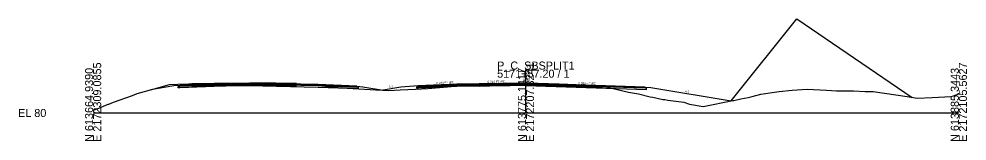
# Model space of a CAD drawing. Extents: x -26 to 1303, y -3010 to 12033.
# Drawn here: x -25.7 to 302.8, y -9.7 to 32.5 of the extents above; entities that cross this region are included whole.
import ezdxf

# ---------------------------------------------------------------- set-up
doc = ezdxf.new("R2010")
doc.units = 0
for name, color, linetype in [('RD_GPK_XS_Cell', 7, 'Continuous'), ('RD_Sketch10', 7, 'Continuous'), ('RD_XS_Base', 7, 'Continuous'), ('RD_XS_Buildup', 7, 'Continuous'), ('RD_XS_ExGround', 7, 'Continuous'), ('RD_XS_ExPaveRet', 7, 'Continuous'), ('RD_XS_Greenside', 7, 'Continuous'), ('RD_XS_Pave', 7, 'Continuous'), ('RD_XS_PaveOvlay_CP', 7, 'Continuous'), ('RD_XS_TieSlope', 7, 'Continuous'), ('RD_XS_TX_Elev_EX', 7, 'Continuous'), ('RD_XS_TX_Elev_PR', 7, 'Continuous'), ('RD_XS_TX_Slope', 7, 'Continuous')]:
    doc.layers.add(name, color=color, linetype=linetype)

msp = doc.modelspace()

# ---------------------------------------------------------------- linework, layer by layer
at = {"layer": 'RD_GPK_XS_Cell'}
for p, q in [((150, 0), (150, 15)), ((0, 0), (150, 0)), ((150, 0), (300, 0))]:
    msp.add_line(p, q, dxfattribs=at)
at = {"layer": 'RD_Sketch10'}
msp.add_lwpolyline([(221.05, 4.2), (243.9, 32.52), (283.83, 5.38)], dxfattribs=at)
at = {"layer": 'RD_XS_Base'}
for p, q in [((42, 9.72), (54, 9.96)), ((54, 9.96), (54, 10.12)), ((54, 10.12), (54, 9.46)), ((54, 9.96), (54, 9.46)), ((78, 9.48), (54, 9.96)), ((54, 9.96), (54, 9.96)), ((126, 9.63), (150, 10.02)), ((150, 10.02), (150, 10.18)), ((150, 10.18), (150, 9.52)), ((150, 10.02), (150, 10.02)), ((191.3, 8.66), (150, 10.02)), ((150, 10.02), (150, 10.02)), ((150, 10.02), (150, 9.52)), ((29.5, 9.22), (30, 9.24)), ((29.5, 8.72), (29.5, 9.22)), ((29.5, 9.22), (29.5, 9.22)), ((30, 8.74), (29.5, 8.72)), ((29.5, 8.72), (29.5, 8.72)), ((29.5, 8.72), (29.5, 8.72)), ((30, 9.24), (42, 9.72)), ((30, 9.24), (30, 9.24)), ((42, 9.22), (30, 8.74)), ((30, 8.74), (30, 8.74)), ((42, 9.72), (42, 9.72)), ((54, 9.46), (42, 9.22)), ((42, 9.22), (42, 9.22)), ((54, 9.46), (54, 9.46)), ((54, 9.46), (54, 9.46)), ((54, 9.46), (78, 8.98)), ((91.44, 8.94), (78, 9.48)), ((78, 9.48), (78, 9.48)), ((78, 8.98), (78, 8.98)), ((78, 8.98), (91.94, 8.42)), ((91.94, 8.92), (91.44, 8.94)), ((91.44, 8.94), (91.44, 8.94)), ((91.94, 8.42), (91.94, 8.92)), ((91.94, 8.92), (91.94, 8.92)), ((91.94, 8.42), (91.94, 8.42)), ((91.94, 8.42), (91.94, 8.42)), ((112.13, 9.08), (112.63, 9.1)), ((112.13, 8.58), (112.13, 9.08)), ((112.13, 9.08), (112.13, 9.08)), ((112.63, 8.6), (112.13, 8.58)), ((112.13, 8.58), (112.13, 8.58)), ((112.13, 8.58), (112.13, 8.58)), ((112.63, 9.1), (126, 9.63)), ((126, 9.13), (112.63, 8.6)), ((112.63, 9.1), (112.63, 9.1)), ((112.63, 8.6), (112.63, 8.6)), ((150, 9.52), (126, 9.13)), ((149.99, 9.52), (191.8, 8.15)), ((150, 9.52), (150, 9.52)), ((150, 9.52), (150, 9.52)), ((191.8, 8.65), (191.3, 8.66)), ((191.3, 8.66), (191.3, 8.66)), ((191.8, 8.15), (191.8, 8.65)), ((191.8, 8.65), (191.8, 8.65)), ((191.8, 8.15), (191.8, 8.15)), ((191.8, 8.15), (191.8, 8.15))]:
    msp.add_line(p, q, dxfattribs=at)
at = {"layer": 'RD_XS_Buildup'}
msp.add_line((64, 10.28), (64, 10.26), dxfattribs=at)
at = {"layer": 'RD_XS_ExGround'}
msp.add_lwpolyline([(0, 1), (1.99, 1.68), (5.18, 3.04), (5.47, 3.09), (7.05, 3.69), (13.64, 6.05), (15.25, 6.73), (21.13, 8.38), (24.37, 9.28), (26.53, 9.89), (29.36, 10), (33, 10.13), (34.22, 10.12), (35.85, 10.14), (41.97, 10.15), (45.88, 10.2), (54.32, 10.28), (63.32, 10.27), (70.48, 10.23), (79.28, 9.35), (86.09, 8.72), (98.02, 8.04), (102.47, 7.81), (106.39, 8), (111.74, 8.25), (116.03, 8.45), (120.03, 8.83), (128.25, 9.53), (132.52, 9.98), (133.83, 10.08), (135.53, 10.1), (137.5, 10.14), (144.47, 10.25), (150.42, 10.35), (161.54, 9.96), (176.28, 9.44), (185.54, 7.24), (189.03, 6.58), (193.08, 5.61), (193.95, 5.43), (197.39, 4.72), (198.07, 4.64), (199.14, 4.44), (204.67, 3.75), (206.61, 3.01), (211.36, 2.29), (221.65, 4.31), (222.01, 4.32), (224.4, 4.87), (227.04, 5.35), (228.43, 5.74), (231.36, 6.48), (236.13, 7.18), (237.75, 7.47), (242.22, 7.88), (247.48, 8.29), (254.1, 7.87), (257.57, 7.72), (259, 7.72), (263.55, 7.62), (267.49, 7.44), (270.27, 7.46), (282.15, 5.66), (285.52, 5.1), (290.76, 5.35), (297.33, 5.67), (298.18, 5.94), (300, 6.67)], dxfattribs=at)
at = {"layer": 'RD_XS_ExPaveRet'}
for points in [[(70.48, 10.23), (70.48, 9.48), (70.48, 9.48), (70.48, 9.48), (70.48, 9.48), (63.32, 9.52), (63.32, 9.52), (54.32, 9.53), (45.88, 9.45), (45.88, 9.45), (41.97, 9.4), (41.97, 9.4), (41.97, 9.4), (35.85, 9.39), (35.85, 9.39), (34.22, 9.37), (34.22, 9.37), (34.22, 10.12), (35.85, 10.14), (35.85, 10.14), (41.97, 10.15), (41.97, 10.15), (41.97, 10.15), (45.88, 10.2), (45.88, 10.2), (54.32, 10.28), (63.32, 10.27), (63.32, 10.27), (70.48, 10.23), (70.48, 10.23), (70.48, 10.23)], [(70.48, 10.23), (63.32, 10.27), (54.32, 10.28), (45.88, 10.2), (41.97, 10.15), (35.85, 10.14), (34.22, 10.12), (34.22, 9.37), (35.85, 9.39), (41.97, 9.4), (45.88, 9.45), (54.32, 9.53), (63.32, 9.52), (70.48, 9.48), (70.48, 9.48), (70.48, 10.23), (70.48, 10.23)], [(176.28, 9.44), (176.28, 9.44), (176.28, 8.69), (176.28, 8.69), (176.28, 8.69), (161.54, 9.21), (161.54, 9.21), (150.42, 9.6), (144.47, 9.5), (144.47, 9.5), (137.5, 9.39), (137.5, 9.39), (135.53, 9.35), (133.83, 9.33), (133.83, 9.33), (133.83, 10.08), (135.53, 10.1), (137.5, 10.14), (137.5, 10.14), (144.47, 10.25), (144.47, 10.25), (150.42, 10.35), (161.54, 9.96), (161.54, 9.96), (176.28, 9.44)], [(161.54, 9.96), (150.42, 10.35), (144.47, 10.25), (137.5, 10.14), (135.53, 10.1), (133.83, 10.08), (133.83, 9.33), (135.53, 9.35), (137.5, 9.39), (144.47, 9.5), (150.42, 9.6), (161.54, 9.21), (176.28, 8.69), (176.28, 9.44), (161.54, 9.96)]]:
    msp.add_lwpolyline(points, dxfattribs=at)
at = {"layer": 'RD_XS_Greenside'}
for p, q in [((28, 9.4), (19.99, 8.06)), ((93.44, 9.1), (100.52, 7.92)), ((106.63, 8.93), (100.52, 7.92)), ((193.3, 8.82), (221.05, 4.2))]:
    msp.add_line(p, q, dxfattribs=at)
at = {"layer": 'RD_XS_Pave'}
for p, q in [((42, 10.04), (30, 9.56)), ((42, 9.88), (30, 9.4)), ((30, 9.4), (42, 9.88)), ((54, 10.28), (42, 10.04)), ((54, 10.12), (42, 9.88)), ((42, 9.88), (54, 10.12)), ((42, 10.04), (42, 10.04)), ((42, 9.72), (54, 9.96)), ((42, 9.88), (42, 9.88)), ((42, 9.88), (42, 9.88)), ((78, 9.8), (54, 10.28)), ((54, 9.96), (54, 10.12)), ((54, 10.12), (78, 9.64)), ((78, 9.64), (54, 10.12)), ((54, 10.12), (54, 9.96)), ((54, 9.96), (54, 9.96)), ((54, 9.96), (54, 9.96)), ((54, 9.96), (78, 9.48)), ((126, 9.95), (112.63, 9.41)), ((150, 10.34), (126, 9.95)), ((150, 10.18), (126, 9.79)), ((126, 9.79), (150, 10.18)), ((126, 9.63), (150, 10.02)), ((191.3, 8.98), (150, 10.34)), ((150, 10.02), (150, 10.18)), ((150, 10.18), (191.3, 8.82)), ((191.3, 8.82), (150, 10.18)), ((150, 10.18), (150, 10.18)), ((150, 10.18), (150, 10.02)), ((150, 10.02), (150, 10.02)), ((150, 10.02), (150, 10.02)), ((150, 10.02), (150, 10.02)), ((150, 10.02), (191.3, 8.66)), ((30, 9.24), (42, 9.72)), ((30, 9.56), (30, 9.56)), ((30, 9.56), (30, 9.4)), ((30, 9.4), (30, 9.4)), ((30, 9.4), (30, 9.24)), ((30, 9.4), (30, 9.4)), ((30, 9.4), (30, 9.4)), ((30, 9.24), (30, 9.24)), ((30, 9.24), (30, 9.24)), ((42, 9.72), (42, 9.72)), ((91.44, 9.26), (78, 9.8)), ((78, 9.8), (78, 9.8)), ((78, 9.64), (78, 9.64)), ((78, 9.64), (91.44, 9.1)), ((91.44, 9.1), (78, 9.64)), ((78, 9.64), (78, 9.64)), ((78, 9.48), (78, 9.48)), ((78, 9.48), (91.44, 8.94)), ((91.44, 9.1), (91.44, 9.26)), ((91.44, 9.26), (91.44, 9.26)), ((91.44, 9.1), (91.44, 9.1)), ((91.44, 9.1), (91.44, 9.1)), ((91.44, 8.94), (91.44, 9.1)), ((91.44, 9.1), (91.44, 9.1)), ((91.44, 8.94), (91.44, 8.94)), ((91.44, 8.94), (91.44, 8.94)), ((126, 9.79), (112.63, 9.26)), ((112.63, 9.26), (126, 9.79)), ((112.63, 9.1), (126, 9.63)), ((112.63, 9.41), (112.63, 9.41)), ((112.63, 9.41), (112.63, 9.26)), ((112.63, 9.26), (112.63, 9.26)), ((112.63, 9.26), (112.63, 9.1)), ((112.63, 9.26), (112.63, 9.26)), ((112.63, 9.26), (112.63, 9.26)), ((112.63, 9.1), (112.63, 9.1)), ((112.63, 9.1), (112.63, 9.1)), ((191.3, 8.82), (191.3, 8.98)), ((191.3, 8.98), (191.3, 8.98)), ((191.3, 8.82), (191.3, 8.82)), ((191.3, 8.82), (191.3, 8.82)), ((191.3, 8.66), (191.3, 8.82)), ((191.3, 8.82), (191.3, 8.82)), ((191.3, 8.66), (191.3, 8.66)), ((191.3, 8.66), (191.3, 8.66))]:
    msp.add_line(p, q, dxfattribs=at)
at = {"layer": 'RD_XS_PaveOvlay_CP'}
for p, q in [((30, 9.56), (42, 10.04)), ((42, 10.04), (54, 10.28)), ((54, 10.28), (78, 9.8)), ((126, 9.95), (112.63, 9.41)), ((150, 10.34), (126, 9.95)), ((191.3, 8.98), (150, 10.34)), ((78, 9.8), (91.44, 9.26)), ((112.63, 9.41), (112.63, 9.41)), ((191.3, 8.98), (191.3, 8.98))]:
    msp.add_line(p, q, dxfattribs=at)
at = {"layer": 'RD_XS_TieSlope'}
for p, q in [((30, 9.56), (28, 9.4)), ((91.44, 9.26), (93.44, 9.1)), ((112.63, 9.41), (106.63, 8.93)), ((191.3, 8.98), (193.3, 8.82))]:
    msp.add_line(p, q, dxfattribs=at)

# ---------------------------------------------------------------- texts
at = {"layer": 'RD_GPK_XS_Cell'}
for s, p in [('E 2172309.0855', (2.8, -10)), ('E 2172207.3241', (152.8, -10)), ('E 2172105.5627', (302.8, -10)), ('N 613664.9390', (0, -10)), ('N 613775.1417', (150, -10)), ('N 613885.3443', (300, -10))]:
    msp.add_text(s, height=2.8, rotation=90, dxfattribs=at).set_placement(p)
for s, p in [('P_C_SBSPLIT1', (140, 15)), ('5171+57.20 / 1', (140, 12.2)), ('EL 80', (-26, -1.4))]:
    msp.add_text(s, height=2.8, dxfattribs=at).set_placement(p)
at = {"layer": 'RD_XS_TX_Elev_EX'}
msp.add_text('90.34', height=0.6, rotation=90, dxfattribs=at).set_placement((149.65, 11.02))
at = {"layer": 'RD_XS_TX_Elev_PR'}
msp.add_text('90.34', height=1, rotation=90, dxfattribs=at).set_placement((151.35, 10.68))
at = {"layer": 'RD_XS_TX_Slope'}
for s, rotation, p in [('0.040 FT./FT.', 2.2906, (118.93, 9.97)), ('0.016 FT./FT.', 0.4422, (136.69, 10.4)), ('0.033 FT./FT.', 358.8542, (168.12, 9.95)), ('6:1', 9.4642, (102.6, 8.63)), ('6:1', 350.5358, (205.14, 7.21))]:
    msp.add_text(s, height=0.75, rotation=rotation, dxfattribs=at).set_placement(p)

doc.saveas('drawing.dxf')
